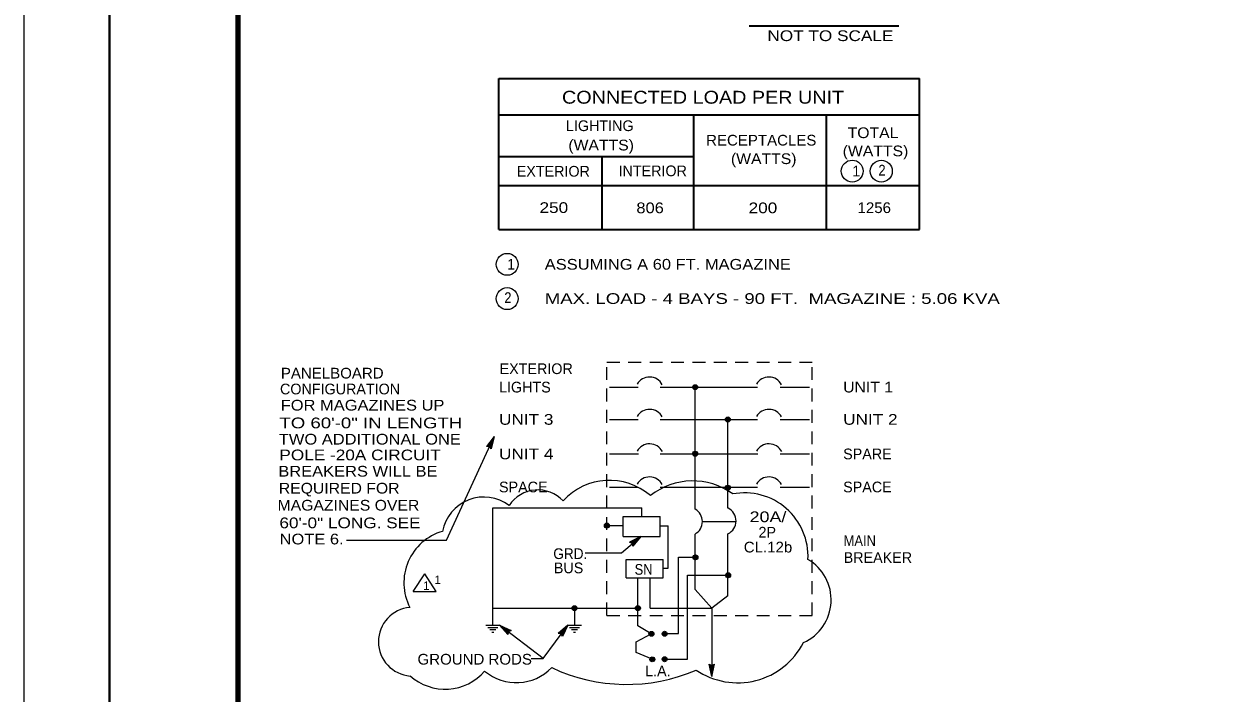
# Model space of a CAD drawing. Extents: x -39.6 to 16.1, y -17.6 to 34.
# Drawn here: x -25.9 to -11.89, y -3.38 to 4.44 of the extents above; entities that cross this region are included whole.
import ezdxf
from ezdxf.enums import TextEntityAlignment as Align

# ---------------------------------------------------------------- set-up
doc = ezdxf.new("R2010")
doc.units = 0
doc.header["$LTSCALE"] = 0.05
doc.linetypes.add('MEDIUM_DASHED', pattern=[4.5, 3, -1.5])
doc.layers.add('1', color=7, linetype='Continuous', lineweight=13)

msp = doc.modelspace()

# ---------------------------------------------------------------- linework, layer by layer
at = {"layer": '1'}
for p, q in [((-25.89821, -17.59158), (-25.89821, 12.40842)), ((-20.41021, -0.38058), (-20.49821, -0.49858)), ((-20.42521, -0.41458), (-20.48321, -0.49158)), ((-20.42521, -0.41458), (-20.44621, -0.50758)), ((-20.46121, -0.49158), (-20.48321, -0.49158)), ((-20.44021, -0.44658), (-20.46721, -0.48458)), ((-20.45721, -0.48458), (-20.46721, -0.48458)), ((-20.44621, -0.50758), (-20.46121, -0.49158)), ((-20.45021, -0.49158), (-20.45721, -0.48458)), ((-20.44021, -0.44658), (-20.45021, -0.49158)), ((-18.92128, -1.73789), (-18.6982, -1.54763)), ((-19.34786, -1.73789), (-18.92128, -1.73789)), ((-20.34521, -2.58158), (-20.21221, -2.64458)), ((-20.34521, -2.58158), (-20.25021, -2.69358)), ((-20.31621, -2.60458), (-20.22921, -2.64558)), ((-20.31621, -2.60458), (-20.25321, -2.67758)), ((-20.28721, -2.62658), (-20.25721, -2.66058)), ((-20.28721, -2.62658), (-20.24521, -2.64558)), ((-20.25521, -2.65158), (-20.25721, -2.66058)), ((-20.24521, -2.64558), (-20.25521, -2.65158)), ((-20.24821, -2.65658), (-20.25321, -2.67758)), ((-20.22921, -2.64558), (-20.24821, -2.65658)), ((-19.83821, -2.97258), (-19.55021, -2.58158)), ((-19.55021, -2.58158), (-19.66021, -2.67958)), ((-19.57221, -2.61158), (-19.64421, -2.67558)), ((-19.59321, -2.64058), (-19.62721, -2.67158)), ((-19.57221, -2.61158), (-19.61221, -2.69858)), ((-19.59321, -2.64058), (-19.61221, -2.68258)), ((-19.55021, -2.58158), (-19.61021, -2.71558)), ((-19.62221, -2.67958), (-19.64421, -2.67558)), ((-19.61821, -2.67358), (-19.62721, -2.67158)), ((-19.61221, -2.69858), (-19.62221, -2.67958)), ((-19.61221, -2.68258), (-19.61821, -2.67358))]:
    msp.add_line(p, q, dxfattribs=at)
at = {"layer": '1', "lineweight": 35}
for p, q in [((-17.43321, 4.41242), (-15.68421, 4.41242)), ((-20.35521, 3.80042), (-15.44121, 3.80042)), ((-20.35521, 2.03742), (-20.35521, 3.80042)), ((-15.44121, 2.03742), (-15.44121, 3.80042)), ((-20.35521, 3.37642), (-15.44121, 3.37642)), ((-18.07621, 2.03742), (-18.07621, 3.37642)), ((-16.52821, 2.03742), (-16.52821, 3.37642)), ((-20.35521, 2.89042), (-18.07621, 2.89042)), ((-19.14921, 2.03742), (-19.14921, 2.89042)), ((-20.35521, 2.54942), (-15.44121, 2.54942)), ((-20.35521, 2.03742), (-15.44121, 2.03742))]:
    msp.add_line(p, q, dxfattribs=at)
at = {"layer": '1', "linetype": 'MEDIUM_DASHED'}
for p, q in [((-19.09321, -2.47058), (-19.09321, 0.48542)), ((-19.09321, 0.48542), (-16.69621, 0.48542)), ((-16.69621, -2.47058), (-16.69621, 0.48542)), ((-19.09321, -2.47058), (-16.69621, -2.47058))]:
    msp.add_line(p, q, dxfattribs=at)
at = {"layer": '1', "lineweight": 25}
for p, q in [((-19.06321, 0.19542), (-18.72621, 0.19542)), ((-18.47221, 0.19542), (-17.33321, 0.19542)), ((-18.06221, -1.22758), (-18.06221, 0.19542)), ((-17.07021, 0.19542), (-16.72721, 0.19542)), ((-19.06321, -0.18158), (-18.72621, -0.18158)), ((-18.47221, -0.18158), (-17.33321, -0.18158)), ((-17.68021, -1.21692), (-17.68021, -0.18158)), ((-17.07021, -0.18158), (-16.72721, -0.18158)), ((-19.06221, -0.58458), (-18.72521, -0.58458)), ((-18.47121, -0.58458), (-17.33221, -0.58458)), ((-17.06921, -0.58458), (-16.72621, -0.58458)), ((-19.06321, -0.97058), (-18.72621, -0.97058)), ((-18.47221, -0.97058), (-17.33321, -0.97058)), ((-17.07021, -0.97058), (-16.72721, -0.97058)), ((-20.42521, -2.58158), (-20.42521, -1.21437)), ((-20.42521, -1.21437), (-18.68324, -1.21437)), ((-18.68324, -1.31558), (-18.68324, -1.21437)), ((-18.90421, -1.31558), (-18.47021, -1.31558)), ((-18.90421, -1.54758), (-18.90421, -1.31558)), ((-18.47021, -1.54758), (-18.47021, -1.31558)), ((-17.97821, -1.37458), (-17.58521, -1.37458)), ((-19.09321, -1.42058), (-18.90421, -1.42058)), ((-18.46221, -1.42358), (-18.37621, -1.42358)), ((-18.06221, -2.16658), (-18.06221, -1.51949)), ((-17.68021, -2.24258), (-17.68021, -1.51804)), ((-18.90421, -1.54758), (-18.47021, -1.54758)), ((-18.6982, -1.54763), (-18.82982, -1.61374)), ((-18.72701, -1.57082), (-18.81279, -1.61416)), ((-18.79325, -1.6241), (-18.81279, -1.61416)), ((-18.75506, -1.59339), (-18.79577, -1.61458)), ((-18.78701, -1.61909), (-18.79577, -1.61458)), ((-18.78771, -1.64532), (-18.79325, -1.6241)), ((-18.6982, -1.54763), (-18.79095, -1.66204)), ((-18.72701, -1.57082), (-18.78771, -1.64532)), ((-18.78385, -1.6294), (-18.78701, -1.61909)), ((-18.75506, -1.59339), (-18.78385, -1.6294)), ((-18.86821, -1.81558), (-18.43721, -1.81558)), ((-18.86821, -2.02958), (-18.86821, -1.81558)), ((-18.43721, -2.02958), (-18.43721, -1.81558)), ((-18.25821, -2.68258), (-18.25821, -1.78958)), ((-18.25721, -1.78958), (-18.06221, -1.78958)), ((-21.35319, -2.19122), (-21.22019, -1.98222)), ((-18.86821, -2.02958), (-18.43721, -2.02958)), ((-18.73321, -2.59158), (-18.73321, -2.02958)), ((-18.58921, -2.38458), (-18.58921, -2.02858)), ((-18.15321, -1.99958), (-17.68021, -1.99958)), ((-18.15321, -2.97958), (-18.15321, -1.99958)), ((-18.06221, -2.16658), (-17.86821, -2.38458)), ((-20.42521, -2.38458), (-18.73321, -2.38458)), ((-19.47021, -2.38458), (-19.47021, -2.58158)), ((-18.58921, -2.38458), (-17.86821, -2.38458)), ((-20.50521, -2.58158), (-20.34521, -2.58158)), ((-20.48321, -2.60958), (-20.36721, -2.60958)), ((-20.46121, -2.63558), (-20.39021, -2.63558)), ((-19.55021, -2.58158), (-19.39021, -2.58158)), ((-19.52821, -2.60958), (-19.41221, -2.60958)), ((-19.50621, -2.63558), (-19.43521, -2.63558)), ((-20.43721, -2.66558), (-20.41321, -2.66558)), ((-19.48221, -2.66558), (-19.45821, -2.66558)), ((-18.74921, -2.90158), (-18.74921, -2.77858)), ((-18.42121, -2.68258), (-18.25821, -2.68258)), ((-18.56521, -2.98158), (-18.74921, -2.90158)), ((-18.42121, -2.97958), (-18.15321, -2.97958)), ((-17.86821, -3.18358), (-17.89921, -3.03958)), ((-17.86821, -3.14658), (-17.88821, -3.05258)), ((-17.88821, -3.05258), (-17.86821, -3.06158)), ((-17.86821, -3.11058), (-17.87821, -3.06558)), ((-17.87821, -3.06558), (-17.86821, -3.06958)), ((-17.86821, -3.18358), (-17.83721, -3.03958)), ((-17.86821, -3.14658), (-17.84821, -3.05258)), ((-17.86821, -3.06158), (-17.84821, -3.05258)), ((-17.86821, -3.11058), (-17.85921, -3.06558)), ((-17.86821, -3.06958), (-17.85921, -3.06558))]:
    msp.add_line(p, q, dxfattribs=at)
at = {"layer": '1', "lineweight": 40}
msp.add_lwpolyline([(-24.89821, -16.59158), (-24.89821, 11.40842), (15.10179, 11.40842), (15.10179, -16.59158)], close=True, dxfattribs=at)
at = {"layer": '1', "lineweight": 90}
msp.add_lwpolyline([(-23.39821, 10.90842), (14.60179, 10.90842), (14.60179, -16.09158), (-23.39821, -16.09158)], close=True, dxfattribs=at)
at = {"layer": '1'}
for points in [[(-22.13321, -1.59258), (-20.96521, -1.59258), (-20.41021, -0.38058), (-20.44221, -0.52458)], [(-20.44221, -0.52458), (-20.46421, -0.49858), (-20.49821, -0.49858)], [(-19.97621, -2.97258), (-19.83821, -2.97258), (-20.34521, -2.58158)], [(-20.21221, -2.64458), (-20.24221, -2.66058), (-20.25021, -2.69358)], [(-19.61021, -2.71558), (-19.62721, -2.68658), (-19.66021, -2.67958)]]:
    msp.add_lwpolyline(points, dxfattribs=at)
at = {"layer": '1', "lineweight": 25}
for points in [[(-18.43721, -1.91758), (-18.37621, -1.91758), (-18.37621, -1.42358)], [(-18.79095, -1.66204), (-18.79947, -1.62912), (-18.82982, -1.61374)], [(-21.35319, -2.19122), (-21.08719, -2.19122), (-21.22019, -1.98222)], [(-17.68021, -2.24258), (-17.86821, -2.38458), (-17.86821, -3.18358)], [(-18.75221, -2.77858), (-18.57521, -2.68358), (-18.73321, -2.59158)], [(-17.89921, -3.03958), (-17.86821, -3.05358), (-17.83721, -3.03958)]]:
    msp.add_lwpolyline(points, dxfattribs=at)
for centre, radius in [((-16.22821, 2.71842), 0.12782), ((-15.88921, 2.71742), 0.12782), ((-20.25721, 1.62942), 0.12782), ((-20.25721, 1.22942), 0.12782), ((-18.06246, 0.19523), 0.02891), ((-18.06246, 0.19523), 0.02242), ((-18.06246, 0.19523), 0.01644), ((-18.06246, 0.19523), 0.0083), ((-17.68046, -0.18177), 0.02891), ((-17.68046, -0.18177), 0.02242), ((-17.68046, -0.18177), 0.01644), ((-17.68046, -0.18177), 0.0083), ((-18.06246, -0.58177), 0.02891), ((-18.06246, -0.58177), 0.02242), ((-18.06246, -0.58177), 0.01644), ((-18.06246, -0.58177), 0.0083), ((-17.68046, -0.97877), 0.02891), ((-17.68046, -0.97877), 0.02242), ((-17.68046, -0.97877), 0.01644), ((-17.68046, -0.97877), 0.0083), ((-19.09346, -1.42077), 0.02891), ((-19.09346, -1.42077), 0.02242), ((-19.09346, -1.42077), 0.01644), ((-19.09346, -1.42077), 0.0083), ((-18.05946, -1.79077), 0.02891), ((-18.05946, -1.79077), 0.02242), ((-18.05946, -1.79077), 0.01644), ((-18.05946, -1.79077), 0.0083), ((-17.67746, -2.00077), 0.02891), ((-17.67746, -2.00077), 0.02242), ((-17.67746, -2.00077), 0.01644), ((-17.67746, -2.00077), 0.0083), ((-19.47046, -2.38477), 0.02891), ((-19.47046, -2.38477), 0.02242), ((-19.47046, -2.38477), 0.01644), ((-19.47046, -2.38477), 0.0083), ((-18.73046, -2.38577), 0.02891), ((-18.73046, -2.38577), 0.02242), ((-18.73046, -2.38577), 0.01644), ((-18.73046, -2.38577), 0.0083), ((-18.57246, -2.68477), 0.02891), ((-18.41846, -2.68377), 0.02891), ((-18.41846, -2.68377), 0.02242), ((-18.57246, -2.68477), 0.02242), ((-18.57246, -2.68477), 0.01644), ((-18.57246, -2.68477), 0.0083), ((-18.41846, -2.68377), 0.01644), ((-18.41846, -2.68377), 0.0083), ((-18.56246, -2.98277), 0.02891), ((-18.56246, -2.98277), 0.02242), ((-18.56246, -2.98277), 0.01644), ((-18.56246, -2.98277), 0.0083), ((-18.41846, -2.98077), 0.02891), ((-18.41846, -2.98077), 0.02242), ((-18.41846, -2.98077), 0.01644), ((-18.41846, -2.98077), 0.0083)]:
    msp.add_circle(centre, radius, dxfattribs=at)
for centre, radius, start, end in [((-18.5946, 0.14525), 0.16819, 28.0799, 149.97146), ((-17.2016, 0.14525), 0.16819, 28.0799, 149.97146), ((-18.5946, -0.23175), 0.16819, 28.0799, 149.97146), ((-17.2016, -0.23175), 0.16819, 28.0799, 149.97146), ((-18.5936, -0.63475), 0.16819, 28.0799, 149.97146), ((-17.2006, -0.63475), 0.16819, 28.0799, 149.97146), ((-19.06337, -1.62351), 0.73118, 49.10289, 137.65574), ((-18.5946, -1.02075), 0.16819, 28.0799, 149.97146), ((-18.09125, -1.69675), 0.79702, 54.07033, 128.24867), ((-17.2016, -1.02075), 0.16819, 28.0799, 149.97146), ((-20.52823, -1.57889), 0.49158, 53.16465, 169.34364), ((-19.89716, -1.40696), 0.40275, 43.24982, 146.63323), ((-17.48478, -1.77863), 0.74038, 357.16427, 100.80354), ((-18.14637, -1.37319), 0.16819, 299.56168, 59.97146), ((-17.75337, -1.36719), 0.16819, 296.2463, 63.32179), ((-20.83919, -2.08776), 0.62398, 106.01358, 207.49878), ((-17.0217, -2.28777), 0.54741, 294.21832, 59.6747), ((-21.35786, -2.77626), 0.4019, 94.96965, 265.6095), ((-17.56602, -2.39138), 0.86468, 235.86908, 332.77202), ((-20.15047, -2.68148), 0.57307, 229.84039, 316.10176), ((-18.8631, -1.2301), 2.0451, 244.68628, 293.39108), ((-20.98168, -2.72106), 0.60976, 228.12578, 319.2056)]:
    msp.add_arc(centre, radius, start, end, dxfattribs=at)

# ---------------------------------------------------------------- texts
at = {"layer": '1'}
for s, height, width, p in [('NOT TO SCALE', 0.125, 1.2, (-16.48321, 4.23642)), ('CONNECTED LOAD PER UNIT', 0.15, 1.15, (-17.97021, 3.50542)), ('TOTAL', 0.125, 1.1, (-15.98571, 3.10342)), ('(WATTS)', 0.125, 1.1, (-19.15971, 2.95942)), ('RECEPTACLES', 0.125, 1.05, (-17.29071, 3.01642)), ('(WATTS)', 0.125, 1.1, (-15.95671, 2.89142)), ('(WATTS)', 0.125, 1.1, (-17.26171, 2.80042)), ('2', 0.125, 0.9, (-15.88071, 2.66642)), ('250', 0.125, 1.2, (-19.71221, 2.22942)), ('806', 0.125, 1.15, (-18.58821, 2.22642)), ('200', 0.125, 1.2, (-17.27071, 2.22642)), ('1256', 0.125, 1.05, (-15.97121, 2.22842)), ('2', 0.125, 0.9, (-20.24871, 1.17842)), ('BREAKERS WILL BE', 0.125, 1.15, (-21.99971, -0.84858)), ('REQUIRED FOR', 0.125, 1.1, (-22.21821, -1.04658)), ('MAGAZINES OVER', 0.125, 1.1, (-22.11021, -1.24558)), ('20A/', 0.125, 1.25, (-17.21171, -1.38058)), ('60\'-0" LONG. SEE', 0.125, 1.2, (-22.09221, -1.45158)), ('NOTE 6.', 0.125, 1.15, (-22.54021, -1.64058)), ('CL.12b', 0.125, 1.05, (-17.21171, -1.73458)), ('GRD.', 0.125, 0.95, (-19.51999, -1.81116)), ('SN', 0.125, 0.9, (-18.66421, -1.99458)), ('GROUND RODS', 0.125, 1.05, (-20.63571, -3.04358))]:
    msp.add_text(s, height=height, dxfattribs=dict(at, width=width)).set_placement(p, align=Align.CENTER)
for s, height, p in [('LIGHTING', 0.125, (-19.17571, 3.18542)), ('EXTERIOR', 0.125, (-19.71821, 2.65342)), ('INTERIOR', 0.125, (-18.55771, 2.65842)), ('1', 0.125, (-16.18132, 2.65642)), ('1', 0.125, (-20.21032, 1.56742)), ('2P', 0.125, (-17.22021, -1.56058)), ('BUS', 0.125, (-19.54033, -1.97699)), ('1', 0.1, (-21.20088, -2.17222)), ('1', 0.1, (-21.06721, -2.10348)), ('L.A.', 0.125, (-18.49771, -3.18058))]:
    msp.add_text(s, height=height, dxfattribs=at).set_placement(p, align=Align.CENTER)
for s, width, p in [('ASSUMING A 60 FT. MAGAZINE', 1.15, (-19.81821, 1.56742)), ('MAX. LOAD - 4 BAYS - 90 FT.  MAGAZINE : 5.06 KVA', 1.3, (-19.81821, 1.16742)), ('PANELBOARD', 1.05, (-22.89921, 0.29642)), ('UNIT 1', 1.1, (-16.33421, 0.13342)), ('FOR MAGAZINES UP', 1.15, (-22.90121, -0.07758)), ('UNIT 3', 1.2, (-20.35221, -0.24358)), ('UNIT 2', 1.2, (-16.33421, -0.24358)), ('TO 60\'-0" IN LENGTH', 1.3, (-22.91621, -0.28458)), ('TWO ADDITIONAL ONE', 1.15, (-22.92321, -0.47458)), ('POLE -20A CIRCUIT', 1.2, (-22.91621, -0.65858)), ('UNIT 4', 1.2, (-20.35221, -0.64658)), ('MAIN', 0.9, (-16.32821, -1.65858))]:
    msp.add_text(s, height=0.125, dxfattribs=dict(at, width=width)).set_placement(p)
for s, p in [('EXTERIOR', (-20.34521, 0.34842)), ('CONFIGURATION', (-22.90921, 0.11142)), ('LIGHTS', (-20.35221, 0.13342)), ('SPARE', (-16.33421, -0.64658)), ('SPACE', (-20.35221, -1.03258)), ('SPACE', (-16.33421, -1.03258)), ('BREAKER', (-16.32821, -1.85658))]:
    msp.add_text(s, height=0.125, dxfattribs=at).set_placement(p)

doc.saveas('drawing.dxf')
